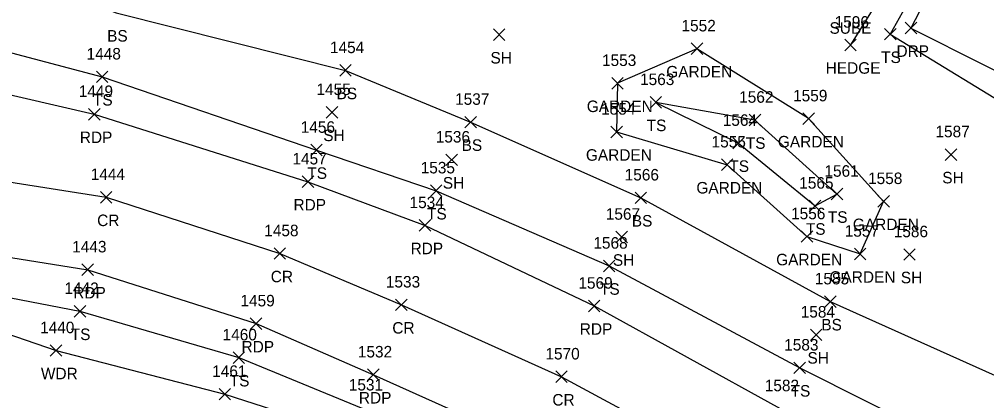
# Model space of a CAD drawing. Extents: x 1586965 to 1590952, y 716317 to 720029.
# Drawn here: x 1587807.3 to 1587975.1, y 719803.4 to 719869.6 of the extents above; entities that cross this region are included whole.
import ezdxf

# ---------------------------------------------------------------- set-up
doc = ezdxf.new("R2010")
doc.units = 0
for name, color, linetype in [('L_A', 7, 'Continuous'), ('L_I', 7, 'Continuous'), ('L_TIC', 7, 'Continuous'), ('LAHR', 7, 'Continuous'), ('LAPB', 7, 'Continuous'), ('LAWA', 7, 'Continuous'), ('LELB', 7, 'Continuous'), ('P_A', 7, 'Continuous'), ('P_I', 7, 'Continuous'), ('P_TIC', 7, 'Continuous'), ('PET', 7, 'Continuous'), ('PRC', 7, 'Continuous'), ('R_A', 7, 'Continuous'), ('R_TIC', 7, 'Continuous'), ('RDP', 7, 'Continuous'), ('U_A', 7, 'Continuous')]:
    doc.layers.add(name, color=color, linetype=linetype)

msp = doc.modelspace()

# ---------------------------------------------------------------- linework, layer by layer
at = {"layer": 'L_TIC'}
for points in [[(1587889.55, 719865.94), (1587891.55, 719867.94)], [(1587891.55, 719865.94), (1587889.55, 719867.94)], [(1587957.41, 719866.03), (1587959.41, 719868.03)], [(1587959.41, 719866.03), (1587957.41, 719868.03)], [(1587923.87, 719863.52), (1587925.87, 719865.52)], [(1587925.87, 719863.52), (1587923.87, 719865.52)], [(1587950.5, 719864.17), (1587952.5, 719866.17)], [(1587952.5, 719864.17), (1587950.5, 719866.17)], [(1587862.89, 719859.75), (1587864.89, 719861.75)], [(1587864.89, 719859.75), (1587862.89, 719861.75)], [(1587820.67, 719858.64), (1587822.67, 719860.64)], [(1587822.67, 719858.64), (1587820.67, 719860.64)], [(1587910.08, 719857.51), (1587912.08, 719859.51)], [(1587912.08, 719857.51), (1587910.08, 719859.51)], [(1587916.73, 719854.2), (1587918.73, 719856.2)], [(1587918.73, 719854.2), (1587916.73, 719856.2)], [(1587860.54, 719852.47), (1587862.54, 719854.47)], [(1587862.54, 719852.47), (1587860.54, 719854.47)], [(1587943.24, 719851.37), (1587945.24, 719853.37)], [(1587945.24, 719851.37), (1587943.24, 719853.37)], [(1587884.59, 719850.77), (1587886.59, 719852.77)], [(1587886.59, 719850.77), (1587884.59, 719852.77)], [(1587933.93, 719851.13), (1587935.93, 719853.13)], [(1587935.93, 719851.13), (1587933.93, 719853.13)], [(1587909.93, 719849.06), (1587911.93, 719851.06)], [(1587911.93, 719849.06), (1587909.93, 719851.06)], [(1587931.08, 719847.12), (1587933.08, 719849.12)], [(1587933.08, 719847.12), (1587931.08, 719849.12)], [(1587857.86, 719845.91), (1587859.86, 719847.91)], [(1587859.86, 719845.91), (1587857.86, 719847.91)], [(1587967.94, 719845.13), (1587969.94, 719847.13)], [(1587969.94, 719845.13), (1587967.94, 719847.13)], [(1587881.29, 719844.22), (1587883.29, 719846.22)], [(1587883.29, 719844.22), (1587881.29, 719846.22)], [(1587929.1, 719843.37), (1587931.1, 719845.37)], [(1587931.1, 719843.37), (1587929.1, 719845.37)], [(1587878.62, 719838.86), (1587880.62, 719840.86)], [(1587880.62, 719838.86), (1587878.62, 719840.86)], [(1587948.16, 719838.28), (1587950.16, 719840.28)], [(1587950.16, 719838.28), (1587948.16, 719840.28)], [(1587914.12, 719837.63), (1587916.12, 719839.63)], [(1587916.12, 719837.63), (1587914.12, 719839.63)], [(1587944.35, 719836.21), (1587946.35, 719838.21)], [(1587946.35, 719836.21), (1587944.35, 719838.21)], [(1587956.25, 719837.01), (1587958.25, 719839.01)], [(1587958.25, 719837.01), (1587956.25, 719839.01)], [(1587910.79, 719830.82), (1587912.79, 719832.82)], [(1587912.79, 719830.82), (1587910.79, 719832.82)], [(1587942.94, 719830.9), (1587944.94, 719832.9)], [(1587944.94, 719830.9), (1587942.94, 719832.9)], [(1587952.19, 719827.87), (1587954.19, 719829.87)], [(1587954.19, 719827.87), (1587952.19, 719829.87)], [(1587960.75, 719827.78), (1587962.75, 719829.78)], [(1587962.75, 719827.78), (1587960.75, 719829.78)], [(1587908.63, 719825.79), (1587910.63, 719827.79)], [(1587910.63, 719825.79), (1587908.63, 719827.79)], [(1587947, 719819.59), (1587949, 719821.59)], [(1587949, 719819.59), (1587947, 719821.59)], [(1587816.81, 719817.92), (1587818.81, 719819.92)], [(1587818.81, 719817.92), (1587816.81, 719819.92)], [(1587944.55, 719813.83), (1587946.55, 719815.83)], [(1587946.55, 719813.83), (1587944.55, 719815.83)], [(1587812.67, 719811.11), (1587814.67, 719813.11)], [(1587814.67, 719811.11), (1587812.67, 719813.11)], [(1587844.39, 719809.87), (1587846.39, 719811.87)], [(1587846.39, 719809.87), (1587844.39, 719811.87)], [(1587941.7, 719808.1), (1587943.7, 719810.1)], [(1587943.7, 719808.1), (1587941.7, 719810.1)], [(1587841.94, 719803.53), (1587843.94, 719805.53)], [(1587843.94, 719803.53), (1587841.94, 719805.53)]]:
    msp.add_lwpolyline(points, dxfattribs=at)
at = {"layer": 'LAHR'}
msp.add_lwpolyline([(1587974.65, 719910.6), (1587965.79, 719888.11), (1587951.5, 719865.17)], dxfattribs=at)
at = {"layer": 'LAPB'}
for points in [[(1587924.87, 719864.52), (1587911.08, 719858.51), (1587910.93, 719850.06), (1587930.1, 719844.37), (1587943.94, 719831.9), (1587953.19, 719828.87), (1587957.25, 719838.01), (1587944.24, 719852.37)], [(1587944.24, 719852.37), (1587924.87, 719864.52)]]:
    msp.add_lwpolyline(points, dxfattribs=at)
at = {"layer": 'LAWA'}
msp.add_lwpolyline([(1587792.66, 719819.32), (1587813.67, 719812.11), (1587842.94, 719804.53), (1587864.87, 719797.45), (1587880.05, 719791.05), (1587889.14, 719781.4), (1587900.01, 719769.71), (1587919.42, 719757.56), (1587933.18, 719752.9), (1587956.11, 719747.4), (1587965.59, 719740.84), (1587976.83, 719735.56), (1587989.17, 719727.65), (1588001.34, 719721.18), (1588025.48, 719708.03), (1588041.3, 719690.98), (1588054.29, 719686.88), (1588082.98, 719668.28), (1588093.79, 719656.56), (1588121.25, 719657.28), (1588128.24, 719644.6), (1588131.95, 719613.69), (1588124.34, 719595.05)], dxfattribs=at)
at = {"layer": 'LELB'}
for points in [[(1587811.93, 719949.52), (1587792.29, 719924.28), (1587790.61, 719906.24), (1587796.42, 719891.05), (1587800.94, 719879.86), (1587824.09, 719870.75), (1587863.89, 719860.75), (1587885.59, 719851.77), (1587915.12, 719838.63), (1587948, 719820.59), (1587984.49, 719804.22), (1588019.19, 719787.78), (1588025.35, 719786.55), (1588029.77, 719787.48), (1588038.8, 719793.55), (1588050.21, 719818.02), (1588057.55, 719835.32), (1588061.37, 719857.52)], [(1587811.93, 719949.52), (1587792.29, 719924.28), (1587790.61, 719906.24), (1587796.42, 719891.05), (1587800.94, 719879.86), (1587824.09, 719870.75), (1587863.89, 719860.75), (1587885.59, 719851.77), (1587915.12, 719838.63), (1587948, 719820.59), (1587984.49, 719804.22), (1588019.19, 719787.78), (1588025.35, 719786.55), (1588029.77, 719787.48), (1588038.8, 719793.55), (1588050.21, 719818.02), (1588057.55, 719835.32), (1588061.37, 719857.52)], [(1587980.38, 719907.57), (1587967.76, 719883.76), (1587958.41, 719867.03), (1587982.59, 719852.2), (1588028.36, 719838.74)], [(1587980.38, 719907.57), (1587967.76, 719883.76), (1587958.41, 719867.03), (1587982.59, 719852.2), (1588028.36, 719838.74)], [(1587785.92, 719905.04), (1587790.72, 719880.4), (1587795.97, 719870.23), (1587799.98, 719865.36), (1587821.67, 719859.64), (1587858.86, 719846.91), (1587879.62, 719839.86), (1587909.63, 719826.79), (1587942.7, 719809.1), (1587978.02, 719791.31), (1588014.84, 719771.38), (1588022.21, 719777.17), (1588033.93, 719779.83), (1588041.77, 719778.33), (1588050.57, 719796.18), (1588059.09, 719817.76), (1588066.51, 719841.34), (1588067.52, 719856.77)], [(1587785.92, 719905.04), (1587790.72, 719880.4), (1587795.97, 719870.23), (1587799.98, 719865.36), (1587821.67, 719859.64), (1587858.86, 719846.91), (1587879.62, 719839.86), (1587909.63, 719826.79), (1587942.7, 719809.1), (1587978.02, 719791.31), (1588014.84, 719771.38), (1588022.21, 719777.17), (1588033.93, 719779.83), (1588041.77, 719778.33), (1588050.57, 719796.18), (1588059.09, 719817.76), (1588066.51, 719841.34), (1588067.52, 719856.77)], [(1587949.16, 719839.28), (1587934.93, 719852.13), (1587917.73, 719855.2), (1587932.08, 719848.12), (1587945.35, 719837.21)], [(1587949.16, 719839.28), (1587934.93, 719852.13), (1587917.73, 719855.2), (1587932.08, 719848.12), (1587945.35, 719837.21)], [(1587945.35, 719837.21), (1587949.16, 719839.28)], [(1587945.35, 719837.21), (1587949.16, 719839.28)], [(1587769.54, 719828.25), (1587817.81, 719818.92), (1587845.39, 719810.87), (1587866.59, 719802.16), (1587894.5, 719791.41), (1587924.64, 719774.45), (1587960.66, 719756.07), (1587994.24, 719738.05), (1588029.81, 719715.93), (1588049.13, 719705.79), (1588061.35, 719699.86), (1588090.7, 719682.25), (1588125.12, 719667.08), (1588163.84, 719653.66), (1588168.64, 719652.01), (1588170.5, 719647.84), (1588169.34, 719638.56), (1588158.94, 719617.68), (1588144.69, 719590.38)], [(1587769.54, 719828.25), (1587817.81, 719818.92), (1587845.39, 719810.87), (1587866.59, 719802.16), (1587894.5, 719791.41), (1587924.64, 719774.45), (1587960.66, 719756.07), (1587994.24, 719738.05), (1588029.81, 719715.93), (1588049.13, 719705.79), (1588061.35, 719699.86), (1588090.7, 719682.25), (1588125.12, 719667.08), (1588163.84, 719653.66), (1588168.64, 719652.01), (1588170.5, 719647.84), (1588169.34, 719638.56), (1588158.94, 719617.68), (1588144.69, 719590.38)]]:
    msp.add_lwpolyline(points, dxfattribs=at)
at = {"layer": 'P_TIC'}
for points in [[(1587819.3, 719852.13), (1587821.3, 719854.13)], [(1587821.3, 719852.13), (1587819.3, 719854.13)], [(1587856.37, 719840.42), (1587858.37, 719842.42)], [(1587858.37, 719840.42), (1587856.37, 719842.42)], [(1587821.37, 719837.71), (1587823.37, 719839.71)], [(1587823.37, 719837.71), (1587821.37, 719839.71)], [(1587876.69, 719832.83), (1587878.69, 719834.83)], [(1587878.69, 719832.83), (1587876.69, 719834.83)], [(1587851.49, 719827.95), (1587853.49, 719829.95)], [(1587853.49, 719827.95), (1587851.49, 719829.95)], [(1587818.16, 719825.14), (1587820.16, 719827.14)], [(1587820.16, 719825.14), (1587818.16, 719827.14)], [(1587872.58, 719819.04), (1587874.58, 719821.04)], [(1587874.58, 719819.04), (1587872.58, 719821.04)], [(1587906.04, 719818.84), (1587908.04, 719820.84)], [(1587908.04, 719818.84), (1587906.04, 719820.84)], [(1587847.36, 719815.77), (1587849.36, 719817.77)], [(1587849.36, 719815.77), (1587847.36, 719817.77)], [(1587867.73, 719806.9), (1587869.73, 719808.9)], [(1587869.73, 719806.9), (1587867.73, 719808.9)], [(1587900.35, 719806.55), (1587902.35, 719808.55)], [(1587902.35, 719806.55), (1587900.35, 719808.55)]]:
    msp.add_lwpolyline(points, dxfattribs=at)
at = {"layer": 'PET'}
for points in [[(1587795.98, 719858.74), (1587820.3, 719853.13), (1587857.37, 719841.42), (1587877.69, 719833.83), (1587907.04, 719819.84), (1587939.32, 719802.03), (1587973.69, 719783.16), (1588008.21, 719763.34), (1588019.61, 719757.58), (1588045.18, 719744.38), (1588072.84, 719731.02), (1588081.8, 719723.85), (1588104.43, 719712.22), (1588133.68, 719697.26), (1588170.87, 719681.39), (1588198.42, 719670.99), (1588228.28, 719659.25)], [(1587769.59, 719834.05), (1587819.16, 719826.14), (1587848.36, 719816.77), (1587868.73, 719807.9), (1587895.82, 719795.75), (1587926.99, 719779.02), (1587962.24, 719759.15), (1587995.65, 719740.56), (1588031.83, 719719.54), (1588060.89, 719703.68), (1588093.53, 719688.06), (1588127.35, 719672.7), (1588165.1, 719657.02), (1588195.68, 719645.12), (1588212.38, 719637.86), (1588219.86, 719635.29)]]:
    msp.add_lwpolyline(points, dxfattribs=at)
at = {"layer": 'PRC'}
msp.add_lwpolyline([(1587770.57, 719846.88), (1587822.37, 719838.71), (1587852.49, 719828.95), (1587873.58, 719820.04), (1587901.35, 719807.55), (1587933.49, 719790.19), (1587967.95, 719771.53), (1588001.84, 719751.71), (1588038.72, 719731.7), (1588068.79, 719715.56), (1588099.02, 719700.65), (1588127.2, 719686.75), (1588167.73, 719669.46), (1588194.58, 719658.84), (1588224.51, 719647.27)], dxfattribs=at)
msp.add_lwpolyline([(1587770.57, 719846.88), (1587822.37, 719838.71), (1587852.49, 719828.95), (1587873.58, 719820.04), (1587901.35, 719807.55), (1587933.49, 719790.19), (1587967.95, 719771.53), (1588001.84, 719751.71), (1588038.72, 719731.7), (1588068.79, 719715.56), (1588099.02, 719700.65), (1588127.2, 719686.75), (1588167.73, 719669.46), (1588194.58, 719658.84), (1588224.51, 719647.27)], dxfattribs=at)
at = {"layer": 'R_TIC'}
for points in [[(1587960.99, 719867.1), (1587962.99, 719869.1)], [(1587962.99, 719867.1), (1587960.99, 719869.1)]]:
    msp.add_lwpolyline(points, dxfattribs=at)
at = {"layer": 'RDP'}
msp.add_lwpolyline([(1587981.59, 719906.83), (1587969.62, 719882.82), (1587961.99, 719868.1), (1587987.74, 719855.09), (1588029.05, 719846.17), (1588038.73, 719873.26)], dxfattribs=at)

# ---------------------------------------------------------------- texts
at = {"layer": 'L_A'}
for s, p in [('BS', (1587822.53, 719865.75)), ('SH', (1587889.04, 719861.94)), ('TS', (1587956.82, 719862.03)), ('HEDGE', (1587947.2, 719860.17)), ('GARDEN', (1587919.54, 719859.52)), ('TS', (1587820.07, 719854.64)), ('BS', (1587862.33, 719855.75)), ('GARDEN', (1587905.75, 719853.51)), ('TS', (1587916.14, 719850.2)), ('SH', (1587860.03, 719848.47)), ('BS', (1587884.03, 719846.77)), ('TS', (1587933.34, 719847.13)), ('GARDEN', (1587938.91, 719847.37)), ('GARDEN', (1587905.6, 719845.06)), ('TS', (1587930.49, 719843.12)), ('TS', (1587857.27, 719841.91)), ('SH', (1587880.78, 719840.22)), ('SH', (1587967.43, 719841.13)), ('GARDEN', (1587924.77, 719839.37)), ('TS', (1587878.03, 719834.86)), ('BS', (1587913.56, 719833.63)), ('TS', (1587947.57, 719834.28)), ('GARDEN', (1587951.91, 719833.01)), ('TS', (1587943.76, 719832.21)), ('SH', (1587910.28, 719826.82)), ('GARDEN', (1587938.61, 719826.9)), ('GARDEN', (1587947.86, 719823.87)), ('SH', (1587960.24, 719823.78)), ('TS', (1587908.04, 719821.79)), ('BS', (1587946.44, 719815.59)), ('TS', (1587816.22, 719813.92)), ('SH', (1587944.04, 719809.83)), ('WDR', (1587811.04, 719807.11)), ('TS', (1587843.8, 719805.87)), ('TS', (1587941.11, 719804.1))]:
    msp.add_text(s, height=2, dxfattribs=at).set_placement(p)
at = {"layer": 'L_I'}
for s, p in [('1596', (1587948.75, 719868.17)), ('1552', (1587922.18, 719867.52)), ('1454', (1587861.19, 719863.75)), ('1448', (1587818.97, 719862.64)), ('1553', (1587908.39, 719861.51)), ('1563', (1587914.99, 719858.2)), ('1455', (1587858.85, 719856.47)), ('1537', (1587882.9, 719854.77)), ('1562', (1587932.19, 719855.13)), ('1559', (1587941.54, 719855.37)), ('1554', (1587908.24, 719853.06)), ('1456', (1587856.11, 719849.91)), ('1564', (1587929.34, 719851.12)), ('1536', (1587879.54, 719848.22)), ('1587', (1587966.24, 719849.13)), ('1555', (1587927.4, 719847.37)), ('1535', (1587876.93, 719842.86)), ('1566', (1587912.32, 719841.63)), ('1561', (1587946.98, 719842.28)), ('1565', (1587942.61, 719840.21)), ('1558', (1587954.55, 719841.01)), ('1567', (1587909.05, 719834.82)), ('1556', (1587941.19, 719834.9)), ('1557', (1587950.5, 719831.87)), ('1586', (1587959, 719831.78)), ('1568', (1587906.89, 719829.79)), ('1585', (1587945.31, 719823.59)), ('1442', (1587815.12, 719821.92)), ('1584', (1587942.86, 719817.83)), ('1440', (1587810.9, 719815.11)), ('1460', (1587842.56, 719813.87)), ('1583', (1587940, 719812.1)), ('1461', (1587840.76, 719807.53)), ('1531', (1587864.46, 719805.16))]:
    msp.add_text(s, height=2, dxfattribs=at).set_placement(p)
at = {"layer": 'P_A'}
for s, p in [('RDP', (1587817.79, 719848.13)), ('RDP', (1587854.86, 719836.42)), ('CR', (1587820.8, 719833.71)), ('RDP', (1587875.18, 719828.83)), ('CR', (1587850.92, 719823.95)), ('RDP', (1587816.65, 719821.14)), ('CR', (1587872.01, 719815.04)), ('RDP', (1587904.53, 719814.84)), ('RDP', (1587845.85, 719811.77)), ('RDP', (1587866.21, 719802.9)), ('CR', (1587899.78, 719802.55))]:
    msp.add_text(s, height=2, dxfattribs=at).set_placement(p)
at = {"layer": 'P_I'}
for s, p in [('1449', (1587817.6, 719856.13)), ('1457', (1587854.68, 719844.42)), ('1444', (1587819.68, 719841.71)), ('1534', (1587875, 719836.83)), ('1458', (1587849.79, 719831.95)), ('1443', (1587816.47, 719829.14)), ('1533', (1587870.89, 719823.04)), ('1569', (1587904.29, 719822.84)), ('1459', (1587845.66, 719819.77)), ('1532', (1587866.03, 719810.9)), ('1570', (1587898.57, 719810.55)), ('1582', (1587936.63, 719805.03))]:
    msp.add_text(s, height=2, dxfattribs=at).set_placement(p)
at = {"layer": 'R_A'}
msp.add_text('DRP', height=2, dxfattribs=at).set_placement((1587959.48, 719863.1))
at = {"layer": 'U_A'}
msp.add_text('SUBE', height=2, dxfattribs=at).set_placement((1587947.86, 719867.11))

doc.saveas('drawing.dxf')
